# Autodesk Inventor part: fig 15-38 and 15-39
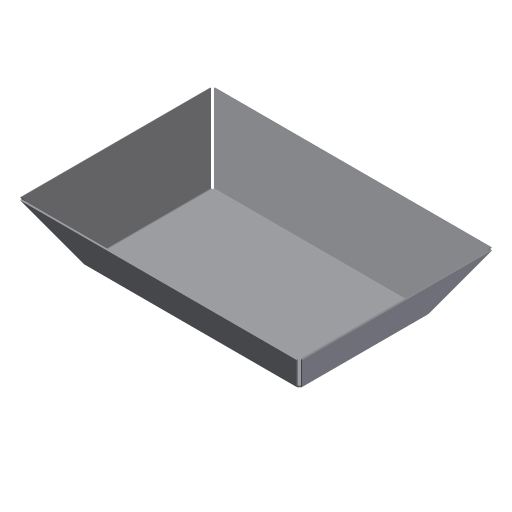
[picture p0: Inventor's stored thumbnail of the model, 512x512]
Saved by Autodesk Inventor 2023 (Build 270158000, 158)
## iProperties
Created: 2007-05
Part Number: fig 15-38 and 15-39
Document SubType Name: Sheet Metal
Designer: Administrator
Density: 1 g/cm^3
Sheet Metal Rule: Default
Material: Generic
Appearance: Default
Author: Administrator
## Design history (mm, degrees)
node "Face1"
  sketch "Sketch1"
    geometry: L1 (-17.365, -15.579)-(32.635, -15.579); L2 (32.635, -15.579)-(32.635, 14.421); L3 (32.635, 14.421)-(-17.365, 14.421); L4 (-17.365, 14.421)-(-17.365, -15.579)
    constraints: 8 end point, 2 parallel, 1 horizontal, 1 perpendicular
    dimensions: "d0" = 30 distance of L3.end L1.start; "d1" = 50 distance of L1.start L1.end
node "Flange1"
body "Solid1"
face "Plate1" dims "d13" = 0.3 (= Thickness)
sketch "Sketch2"
  geometry: L1 through (-15, 0) direction (1, 0); L2 through (0, 7.5) direction (3.7e-17, 1); L3 (0, 15)-(-30, 15); L4 (-30, 15)-(-30, 0)
  constraints: 6 end point, 1 horizontal, 1 perpendicular, 1 vertical
face "Plate2" dims "d3" = 0.3 (= BendReliefWidth), "d4" = 0.15 (= BendReliefDepth), "d5" = 0.6 (= MinimumRemnant), "d6" = 0.3 (= BendRadius), "d7" = 15, "d8" = 60 deg, "d9" = 0.3 (= BendRadius), "d10" = 1.2 (= CornerReliefSize), "d11" = 0.5, "d12" = 0.3 (= JacobiRadiusSize), "d13" = 0.3 (= Thickness), "SeamGap" = 0.01
bend "Bend1" dims "d3" = 0.3 (= BendReliefWidth), "d4" = 0.15 (= BendReliefDepth), "d5" = 0.6 (= MinimumRemnant), "d6" = 0.3 (= BendRadius), "d7" = 15, "d8" = 60 deg, "d9" = 0.3 (= BendRadius), "d13" = 0.3 (= Thickness), "SeamGap" = 0.01
feature "Corner1" dims "d7" = 15, "d8" = 60 deg, "d10" = 1.2 (= CornerReliefSize), "d11" = 0.5, "d12" = 0.3 (= JacobiRadiusSize)
other parameters: "Thickness" = 0.3, "BendRadius" = 0.3 (= Thickness), "BendReliefWidth" = 0.3 (= Thickness), "BendReliefDepth" = 0.15 (= 0.5 x Thickness), "CornerReliefSize" = 1.2 (= 4 x Thickness), "MinimumRemnant" = 0.6 (= 2 x Thickness), "TransitionRadius" = 0.3 (= BendRadius), "JacobiRadiusSize" = 0.3 (= Thickness), "d2" = 0.3 (= BendRadius), "GapSize" = 0.3 (= Thickness)
